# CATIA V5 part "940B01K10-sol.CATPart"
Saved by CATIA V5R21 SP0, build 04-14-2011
Part number: 940B01K10-sol
Bounding box of the stored display mesh (mm): x -77.949 to 0.051, y -15.698 to 19.302, z -6.85 to 7.15
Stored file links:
  C:\Users\ALI OZGUN\Desktop\alhan\940B01K10-sol.CATPart
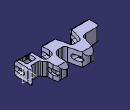
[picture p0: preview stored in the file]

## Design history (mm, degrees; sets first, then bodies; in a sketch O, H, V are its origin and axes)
Set1 "CURVE"
  DatumCurve1 to DatumCurve105
Set2 "SURFACE"
  Plane1: type 1Curve, Element1 DatumCurve19
  Sketch1 on Plane1, origin (0, 0, -3.1959), H (1, 0, 0), V (0, -1, 0)
    line L1 (49.4472, 15.9983) -> (32.7694, 15.9983)
    line L2 (48.5473, -19.0017) -> (65.7661, -19.0017)
    line L3 (-61.2339, -0.5841) -> (-61.2339, 15.0809)
    line L4 (65.7661, -19.0017) -> (65.7661, 3.0782)
    point P1 (65.7661, -19.0017)
    line L5 (49.4472, 15.9983) -> (49.0081, 3.1001)
    line L6 (49.0081, 3.1001) -> (53.2715, -2.5577)
    line L7 (53.2715, -2.5577) -> (61.843, -2.5577)
    point P2 (49.0081, 3.1001)
    point P3 (53.2715, -2.5577)
    point P4 (49.4472, 15.9983)
    line L8 (61.843, -2.5577) -> (65.7661, 3.0782)
    point P5 (61.843, -2.5577)
    point P6 (65.7661, 3.0782)
    reference intersected line E1 through (0, 0) direction (0, 1) from yz-plane
    reference intersected line E2 through (0, 0) direction (0, 1) from yz-plane
    construction line L9 (41.1083, 0) -> (41.1083, 12.9106)
    construction line L10 (41.1083, 12.9106) -> (46.3559, 12.9106)
    construction line L11 (46.3559, 12.9106) -> (46.3559, 3.0133)
    construction line L12 (46.3559, 3.0133) -> (41.1083, 3.0133)
    point P7 (46.3559, 12.9106)
    point P8 (46.3559, 3.0133)
    point P9 (41.1083, 12.9106)
    point P10 (41.1083, 3.0133)
    line L13 (41.1083, 0) -> (50.5276, 0)
    line L14 (48.5473, -19.0017) -> (50.5276, 0)
    point P11 (50.5276, 0)
    point P12 (41.1083, 0)
    point P13 (48.5473, -19.0017)
    point P14 (35.8607, 12.9106)
    point P15 (41.1083, 12.9106)
    construction line L15 (41.1083, 12.9106) -> (35.8607, 12.9106)
    point P16 (35.8607, 3.0133)
    construction line L16 (35.8607, 12.9106) -> (35.8607, 3.0133)
    point P17 (41.1083, 3.0133)
    construction line L17 (35.8607, 3.0133) -> (41.1083, 3.0133)
    point P18 (31.6891, 0)
    point P19 (41.1083, 0)
    line L18 (41.1083, 0) -> (31.6891, 0)
    point P20 (33.6694, -19.0017)
    line L19 (33.6694, -19.0017) -> (31.6891, 0)
    point P21 (16.4506, -19.0017)
    line L20 (33.6694, -19.0017) -> (16.4506, -19.0017)
    point P22 (16.4506, 3.0782)
    line L21 (16.4506, -19.0017) -> (16.4506, 0)
    point P23 (20.3736, -2.5577)
    line L22 (20.3736, -2.5577) -> (16.5464, 2.9405)
    point P24 (28.9451, -2.5577)
    line L23 (28.9451, -2.5577) -> (20.3736, -2.5577)
    point P25 (33.2086, 3.1001)
    line L24 (33.2086, 3.1001) -> (28.9451, -2.5577)
    point P26 (32.7694, 15.9983)
    line L25 (32.7694, 15.9983) -> (33.2086, 3.1001)
    axis line L26 (24.8802, -15.8106) -> (24.8802, 20.8842)
    line L27 (16.991, 15.9983) -> (16.5464, 2.9405)
    point P29 (13.8998, 3.0133)
    point P30 (13.8998, 12.9106)
    construction line L28 (13.8998, 12.9106) -> (13.8998, 3.0133)
    point P31 (8.6521, 0)
    line L29 (8.6521, 0) -> (16.4506, 0)
    point P32 (8.6521, 0)
    line L30 (8.6521, 0) -> (-0.2618, 0)
    point P33 (3.4045, 3.0133)
    point P34 (3.4045, 12.9106)
    construction line L31 (3.4045, 12.9106) -> (3.4045, 3.0133)
    point P35 (8.6521, 3.0133)
    construction line L32 (3.4045, 3.0133) -> (8.6521, 3.0133)
    point P36 (8.6521, 3.0133)
    construction line L33 (13.8998, 3.0133) -> (8.6521, 3.0133)
    point P37 (8.6521, 12.9106)
    construction line L34 (8.6521, 12.9106) -> (3.4045, 12.9106)
    point P38 (8.6521, 12.9106)
    construction line L35 (8.6521, 12.9106) -> (13.8998, 12.9106)
    point P39 (0.3133, 15.9983)
    line L36 (0.3133, 15.9983) -> (0.7524, 3.1001)
    line L37 (0.7524, 3.1001) -> (-3.8134, -2.9589)
    line L38 (16.991, 15.9983) -> (0.3133, 15.9983)
    line L39 (-0.2618, 0) -> (0.5916, -19.0017)
    line L40 (-12.1477, -5.1469) -> (-12.4932, -19.0017)
    line L41 (-3.8134, -2.9589) -> (-12.4906, -2.9589)
    line L42 (-12.4906, -2.9589) -> (-12.6654, 12.1222)
    line L43 (-29.6656, -3.0126) -> (-25.0164, 15.9983)
    line L44 (-39.0662, -3.1542) -> (-29.6656, -3.0126)
    line L45 (-44.327, 15.3928) -> (-39.0662, -3.1542)
    line L46 (-43.9186, 0.391) -> (-38.7475, -19.0017)
    line L47 (-43.9186, 0.391) -> (-61.2339, -0.5841)
    line L48 (-61.2339, 15.0809) -> (-44.327, 15.3928)
    line L49 (-16.4275, 15.9983) -> (-25.0164, 15.9983)
    line L50 (-16.4275, 15.9983) -> (-12.6654, 12.1222)
    line L51 (-24.9197, 0.2086) -> (-29.3974, -19.0017)
    line L52 (-24.9197, 0.2086) -> (-16.3942, 0.2086)
    line L53 (-16.3942, 0.2086) -> (-12.1477, -5.1469)
    line L54 (-29.3974, -19.0017) -> (-38.7475, -19.0017)
    line L55 (0.5916, -19.0017) -> (-12.4932, -19.0017)
    distance L2 L1 = 35
    distance L3 L4 = 127
    angle E1 L5 = 1.95
    angle E2 L6 = 37
    horizontal: L1 H, L2 H, L7 H, L10 H, L12 H, L13 H, L38 H, L41 H, L49 H, L52 H
    fix: L1, L9
    vertical: L3 V, L4 V, L9 V, L11 V, L26 V
    coincidence: P10 L9, L1 L38, P22 L22, P22 L21, L38 L49, L20 L54, L20 L55
    symmetry: P7 P14 L9, P9 P15 L9, L10 L15 L9, P8 P16 L9, L11 L16 L9, P10 P17 L9, L12 L17 L9, P11 P18 L9, P12 P19 L9, L13 L18 L9, P13 P20 L9, L14 L19 L9, P1 P21 L9, L2 L20 L9, P6 P22 L9, L4 L21 L9, P5 P23 L9, L8 L22 L9, P3 P24 L9, L7 L23 L9, P2 P25 L9, L6 L24 L9, P4 P26 L9, L5 L25 L9, L25 L27 L26, P16 P29 L26, P14 P30 L26, L16 L28 L26, P19 P31 L26, L18 L29 L26, P12 P32 L26, L13 L30 L26, P8 P33 L26, P7 P34 L26, L11 L31 L26, P10 P35 L26, L12 L32 L26, P17 P36 L26, L17 L33 L26, P9 P37 L26, L10 L34 L26, P15 P38 L26, L15 L35 L26, P4 P39 L26, L5 L36 L26, L6 L37 L26
  Sweep1: type Segment, GuideCrv Sketch1, Length1 4, Length2 5, Angle -1, DraftDirection (0, 0, 1)
  Sketch2 on yz-plane, origin (0, 0, 0), H (0, 1, 0), V (0, 0, 1)
    line L1 (-24.9191, -6.9968) -> (50.389, -6.9968)
    horizontal: L1 H
  Extrude1: Element1 Sketch2, Lim1 80, Lim2 80
  Trim1: Trimmed (Sweep1; Extrude1)
  Sketch3 on yz-plane, origin (0, 0, 0), H (0, 1, 0), V (0, 0, 1)
    line L1 (-48.3055, 0) -> (52.6647, 0)
    horizontal: L1 H
    coincidence: O L1
  Extrude2: Element1 Sketch3, Lim1 80, Lim2 80
  Trim2: Trimmed (Trim1; Extrude2)
  Extrude3: Element1 Sketch7, Lim1 10, Lim2 10
  Translate1: Direction (1, 0, 0), Length 32.6, ToTransfor Extrude3
  Extrude4: Element1 Sketch8, Lim1 10, Lim2 10
  Translate2: Direction (1, 0, 0), Length 32.8, ToTransfor Extrude4
  Sweep2: type Segment, GuideCrv Sketch11, Length1 10, Length2 5, Angle -1, DraftDirection (0, 0, 1)
  Translate3: Direction (1, 0, 0), Length -32.8, ToTransfor Sweep2
  Sketch4 on face of CloseSurface1, origin (0, 0, 0), H (1, 0, 0), V (0, 1, 0)
    line L1 (-3.8486, 19.8441) -> (1.0015, 13.5162)
  Sweep3: type Segment, GuideCrv Sketch4, Length1 10, Length2 5, Angle 1, DraftDirection (0, 0, 1)
  Plane2: type 1Curve, Element1 DatumCurve99
  Sketch5 on Plane2, origin (0, 0, -5.2979), H (1, 0, 0), V (0, -1, 0)
    line L1 (-37.6706, -7.3878) -> (-35.3775, -14.835)
    line L2 (-32.6098, -14.835) -> (-30.9175, -7.3878)
    offset line E2 (-36.4878, -14.835) -> (-31.7318, -14.835) from edge [face of Mirror1 | face of CloseSurface1]
    offset line E3 (-35.3775, -14.835) -> (-32.6098, -14.835) from edge [face of Mirror1 | face of CloseSurface1]
    line L3 (-37.6706, -7.3878) -> (-30.9175, -7.3878)
    point P5 (-36.4878, -7.3878)
    point P6 (-31.7318, -7.3878)
    construction line L4 (-36.4878, -14.835) -> (-36.4878, -7.3878)
    construction line L5 (-31.7318, -14.835) -> (-31.7318, -7.3878)
    distance E2 L3 = 7.4472
    perpendicularity: L4 E2, L4 L3, L5 E2, L5 L3
    coincidence: P5 L3, P6 L3
  Sweep4: type Segment, GuideCrv Sketch5, Length1 5, Length2 5, Angle -1, DraftDirection (0, 0, 1)
  Sketch6 on yz-plane, origin (0, 0, 0), H (0, 1, 0), V (0, 0, 1)
    line L1 (-47.946, -0.4507) -> (26.6531, -0.4507)
    horizontal: L1 H
  Extrude5: Element1 Sketch6, Lim1 100, Lim2 100
  Trim3: Trimmed (Sweep4; Extrude5)
  Sweep5: type Segment, GuideCrv Sketch12, Length1 5, Length2 5, Angle -1, DraftDirection (0, 0, 1)
  Trim4: Trimmed (Extrude5; Sweep5)
  MultiExtract1: ListOfMultiExtractConstraints (MultiExtractConstraint face of Split9; MultiExtractConstraint face of Fillet45; MultiExtractConstraint face of Split9; MultiExtractConstraint face of Fillet47; MultiExtractConstraint face of Split9; MultiExtractConstraint face of Split9; MultiExtractConstraint face of Fillet49; MultiExtractConstraint face of Fillet48; MultiExtractConstraint face of Fillet46; MultiExtractConstraint face of Split9)
  Extrapol1: ToExtrapol edge of MultiExtract1, Support MultiExtract1, Length 10
  Extrapol2: ToExtrapol edge [end face of Pocket4 | face of Pocket5 from Sketch15.E2], Support face of Pocket5 from Sketch15.E2, Length 10
  Trim5: Trimmed (Extrapol1; Extrapol2)
  Extrapol3: ToExtrapol edge of MultiExtract1, Support Trim5, Length 1
  Extrapol4: ToExtrapol edge [face of Pocket4 from Sketch14.L2 | face of CloseSurface1], Support face of Pocket4 from Sketch14.L2, Length 5
  Extrapol5: ToExtrapol edge [face of Pocket4 from Sketch14.L1 | face of Mirror1], Support face of Pocket4 from Sketch14.L1, Length 5
  Extrapol6: ToExtrapol edge [face of Mirror1 | face of Pocket4 from Sketch14.L4], Support face of Pocket4 from Sketch14.L4, Length 5
  Trim6: Trimmed (Extrapol6; Extrapol5; Extrapol4)
  Extrapol7: ToExtrapol edge [face of CloseSurface1 | face of Split10], Support face of Split10, Length 5
  Trim7: Trimmed (Extrapol7; Trim6)
  Extrapol8: ToExtrapol edge [face of CloseSurface1 | face of Pocket4 from Sketch14.L3], Support face of Pocket4 from Sketch14.L3, Length 5
  Trim8: Trimmed (Extrapol8; Trim7)
Set3
  CLDGeom1 "4_1.1"
  Plane3: type Offset, RefPlane yz-plane, Offset -63
  Plane4: type Offset, RefPlane face of Solid3, Offset 0.2, reversed
Body1 (main body)
  CloseSurface1: CloseElement Trim2
  Sketch7 on face of CloseSurface1, origin (0, 0, -6.9968), H (1, 0, 0), V (0, -1, 0)
    line L1 (3.5232, 12.867) -> (13.7904, 12.867)
    line L2 (13.7904, 12.867) -> (13.7904, 3.1238)
    line L3 (13.7904, 3.1238) -> (3.5232, 3.1238)
    line L4 (3.5232, 3.1238) -> (3.5232, 12.867)
    horizontal: L1 H, L3 H
    vertical: L2 V, L4 V
    fix: L4, L1
  Split1: SplitPlane Extrude3
  Split2: SplitPlane Translate1
  Sketch8 on face of CloseSurface1, origin (0, 0, -6.9968), H (1, 0, 0), V (0, -1, 0)
    line L1 (19.6709, -6.2611) -> (30.062, -6.2611)
    line L2 (30.062, -6.2611) -> (30.062, -15.6449)
    line L3 (30.062, -15.6449) -> (19.6709, -15.6449)
    line L4 (19.6709, -15.6449) -> (19.6709, -6.2611)
    horizontal: L1 H, L3 H
    vertical: L2 V, L4 V
    fix: L1, L4, L2
  Split3: SplitPlane Translate2
  Split4: SplitPlane Extrude4
  Sketch9 on face of CloseSurface1, origin (0, 0, -6.9968), H (1, 0, 0), V (0, -1, 0)
    line L1 (-8.0734, -6.1533) -> (-4.0044, -6.1533)
    line L2 (-4.0044, -6.1533) -> (-4.0044, -14.5157)
    line L3 (-4.0044, -14.5157) -> (-8.0734, -14.5157)
    line L4 (-8.0734, -14.5157) -> (-8.0734, -6.1533)
    horizontal: L1 H, L3 H
    vertical: L2 V, L4 V
  Pocket1: profile Sketch9, direction (0, 0, 1), length 20
  Sketch10 on face of CloseSurface1, origin (0, 0, -6.9968), H (1, 0, 0), V (0, -1, 0)
    line L1 (-16.7652, 4.7837) -> (-23.421, 4.7837)
    line L2 (-21.5701, 11.8402) -> (-16.7652, 11.8402)
    line L3 (-16.7652, 11.8402) -> (-16.7652, 4.7837)
    line L4 (-23.421, 4.7837) -> (-21.5701, 11.8402)
    horizontal: L1 H, L2 H
    vertical: L3 V
  Pocket2: profile Sketch10, direction (0, 0, 1), length 20
  Draft1: Angle 1, Neutral face of CloseSurface1, PullDir face of CloseSurface1, SupportToDraft (face of Split3; face of Split3; face of Split3; face of Split3; face of Split2; face of Split2; face of Split2; face of Split2; face of Split4; face of Split4; face of Split4; face of Split4; face of Split1; face of Split1; face of Split1; face of Split1; face of Pocket1 from Sketch9.L2; face of Pocket1 from Sketch9.L4; face of Pocket1 from Sketch9.L3; face of Pocket1 from Sketch9.L1; face of Pocket2 from Sketch10.L1; face of Pocket2 from Sketch10.L3; face of Pocket2 from Sketch10.L2; face of Pocket2 from Sketch10.L4)
  Chamfer1: length 2.85, angle 44, on edge [face of CloseSurface1 | face of CloseSurface1] (x8)
  Thickness1: Face (face of Chamfer1; face of Chamfer1; face of Chamfer1; face of Chamfer1), Thickness 0.15
  Thickness2: Face (face of Chamfer1; face of Chamfer1; face of Chamfer1; face of Chamfer1), Thickness 0.4
  Sketch11 on face of CloseSurface1, origin (0, 0, 0), H (1, 0, 0), V (0, 1, 0)
    line L1 (57.6565, 24.4948) -> (67.109, 12.822)
    line L2 (46.3763, 10.5649) -> (57.6565, 24.4948)
    angle V L2 = 39
    angle L1 V = 39
  Split5: SplitPlane Sweep2
  Split6: SplitPlane Translate3
  Split7: SplitPlane Sweep3
  Thickness3: Face face of Split7, Thickness -0.1
  Fillet1: radius 0.75, on edge [face of CloseSurface1 | face of CloseSurface1]
  Fillet2: radius 4, on edge [face of Split6 | face of CloseSurface1]; edge [face of Split5 | face of CloseSurface1]
  Fillet3: radius 4.5, on edge [face of Split6 | face of CloseSurface1]; edge [face of Split5 | face of CloseSurface1]
  Fillet4: radius 4.5, on edge [face of Split6 | face of CloseSurface1]; edge [face of Split5 | face of CloseSurface1]
  Fillet5: radius 4.5, on edge [face of CloseSurface1 | face of Split5]; edge [face of CloseSurface1 | face of Split6]
  Fillet6: radius 3.5, on edge [face of CloseSurface1 | face of CloseSurface1] (x4)
  Fillet7: radius 3, on edge [face of Split7 | face of CloseSurface1]
  Fillet8: radius 3, on edge [face of Split7 | face of CloseSurface1]
  Fillet9: radius 4, on edge [face of CloseSurface1 | face of CloseSurface1]
  Fillet10: radius 3, on edge [face of CloseSurface1 | face of CloseSurface1]
  Fillet11: radius 3, on edge [face of CloseSurface1 | face of CloseSurface1]
  Fillet12: radius 3, on edge [face of CloseSurface1 | face of CloseSurface1]
  Fillet13: radius 3, on edge [face of CloseSurface1 | face of CloseSurface1]
  Fillet14: radius 3, on edge [face of CloseSurface1 | face of CloseSurface1]
  Fillet15: radius 3, on edge [face of CloseSurface1 | face of CloseSurface1]
  Fillet16: radius 3, on edge [face of CloseSurface1 | face of CloseSurface1]
  Fillet17: radius 3, on edge [face of CloseSurface1 | face of CloseSurface1] (x2)
  Fillet18: radius 0.75, on edge [face of CloseSurface1 | face of CloseSurface1]
  Fillet19: radius 0.75, on edge [face of CloseSurface1 | face of CloseSurface1]
  Fillet20: radius 3, on edge [face of CloseSurface1 | face of CloseSurface1] (x4)
  Fillet21: radius 0.75, on edge [face of CloseSurface1 | face of CloseSurface1] (x2)
  Fillet22: radius 3, on edge [face of CloseSurface1 | face of CloseSurface1] (x2)
  Fillet23: radius 4, on edge [face of CloseSurface1 | face of CloseSurface1]
  Fillet24: radius 3, on edge [face of CloseSurface1 | face of CloseSurface1]
  Fillet25: radius 1.5, on edge [face of CloseSurface1 | face of CloseSurface1] (x2)
  Fillet26: radius 3, on edge [face of CloseSurface1 | face of CloseSurface1] (x2)
  Fillet27: radius 3, on edge [face of CloseSurface1 | face of CloseSurface1]
  Fillet28: radius 0.5, on edge [face of CloseSurface1 | face of CloseSurface1]
  Fillet29: radius 0.5, on edge [face of CloseSurface1 | face of CloseSurface1]
  Fillet30: radius 2.75, on edge [face of Split4 | face of Split4] (x2); edge [face of Split3 | face of Split3] (x2)
  Fillet31: radius 2, on edge [face of Split4 | face of Split4] (x2); edge [face of Split3 | face of Split3] (x2)
  Fillet32: radius 2.75, on edge [face of Split2 | face of Split2] (x2)
  Fillet33: radius 2, on edge [face of Split2 | face of Split2] (x2)
  Fillet34: radius 1.5, on edge [face of Split1 | face of Split1] (x2)
  Fillet35: radius 1.75, on edge [face of Split1 | face of Split1] (x2)
  TritangentFillet1: Face1 face of Pocket1 from Sketch9.L4, Face2 face of Pocket1 from Sketch9.L2, RemoveFace face of Pocket1 from Sketch9.L1
  TritangentFillet2: Face1 face of Pocket1 from Sketch9.L4, Face2 face of Pocket1 from Sketch9.L2, RemoveFace face of Pocket1 from Sketch9.L3
  Fillet36: radius 1.75, on edge [face of Pocket2 from Sketch10.L2 | face of Pocket2 from Sketch10.L3]
  Fillet37: radius 1, on edge [face of Pocket2 from Sketch10.L4 | face of Pocket2 from Sketch10.L2]
  Fillet38: radius 1.5, on edge [face of Pocket2 from Sketch10.L4 | face of Pocket2 from Sketch10.L1]
  Fillet39: radius 1.75, on edge [face of Pocket2 from Sketch10.L3 | face of Pocket2 from Sketch10.L1]
  Fillet40: radius 0.5, on edge [face of CloseSurface1 | face of CloseSurface1] (x8)
  Fillet41: radius 0.5, on edge [face of Chamfer1 | face of CloseSurface1]
  Fillet42: radius 0.5, on edge [face of Chamfer1 | face of CloseSurface1]
  Fillet43: radius 0.5, on edge [face of Chamfer1 | face of CloseSurface1] (x2)
  Fillet44: radius 0.5, on edge [face of Chamfer1 | face of CloseSurface1] (x4)
  Thickness4: Face face of CloseSurface1, Thickness 0.15
  Mirror1: of the body so far, about face of CloseSurface1
  Split8: SplitPlane Trim3
  Sketch12 on Plane2, origin (0, 0, -5.2979), H (1, 0, 0), V (0, -1, 0)
    line L1 (-57.1409, 11.1692) -> (-47.5031, 11.1692)
    line L2 (-46.3543, 7.2877) -> (-46.3543, 4.9902)
    line L3 (-46.3543, 4.9902) -> (-57.1409, 4.9902)
    line L4 (-57.1409, 4.9902) -> (-57.1409, 11.1692)
    line L5 (-47.5031, 11.1692) -> (-46.3543, 7.2877)
    horizontal: L1 H, L3 H
    vertical: L2 V, L4 V
  Split9: SplitPlane Trim4
  Fillet45: radius 2, on edge [face of Split9 | face of Split9]
  Fillet46: radius 2, on edge [face of Split9 | face of Split9]
  Fillet47: radius 1.9, on edge [face of Split9 | face of Split9]
  Fillet48: radius 2, on edge [face of Split9 | face of Split9]
  Fillet49: radius 2, on edge [face of Split9 | face of Split9]
  Fillet50: radius 2, on edge [face of Split8 | face of Split8]
  Fillet51: radius 2, on edge [face of Split8 | face of Split8]
  Fillet52: radius 1.5, on edge [face of Split8 | face of Split8] (x2)
  Sketch13 on yz-plane, origin (0, 0, 0), H (0, 1, 0), V (0, 0, 1)
    line L1 (4.7142, -2.0988) -> (16.0181, -2.0988)
    line L2 (16.0181, -2.0988) -> (16.0181, 2.7411)
    line L3 (16.0181, 2.7411) -> (4.7142, 2.7411)
    line L4 (4.7142, 2.7411) -> (4.7142, -2.0988)
    horizontal: L1 H, L3 H
    vertical: L2 V, L4 V
  Pocket3: profile Sketch13, direction (-1, 0, 0), length 111, opposite side length 100
  Sketch14 on yz-plane, origin (0, 0, 0), H (0, 1, 0), V (0, 0, 1)
    line L1 (-13.6557, 2.8812) -> (-2.4057, 2.8812)
    line L2 (-2.4057, 2.8812) -> (-2.4057, -2.1188)
    line L3 (-2.4057, -2.1188) -> (-13.6557, -2.1188)
    line L4 (-13.6557, -2.1188) -> (-13.6557, 2.8812)
    distance L1 L3 = 5
    distance L4 L2 = 11.25
    horizontal: L1 H, L3 H
    vertical: L2 V, L4 V
    fix: L1
  Pocket4: profile Sketch14, direction (-1, 0, 0), length 55, opposite side length 100
  Sketch15 on Plane3, origin (-63, 0, 0), H (0, 1, 0), V (0, 0, 1)
    projected line E1 (16.0181, 2.7411) -> (4.7142, 2.7411) from edge [face of Pocket3 from Sketch13.L3 | face of Mirror1]
    projected line E2 (2.9895, 2.7411) -> (-6.2509, 2.7411) from edge [face of Pocket3 from Sketch13.L3 | face of Mirror1]
    projected line E3 (16.0181, -2.0988) -> (4.7142, -2.0988) from edge [face of CloseSurface1 | face of Pocket3 from Sketch13.L1]
    projected line E4 (2.9895, -2.0988) -> (-6.2509, -2.0988) from edge [face of CloseSurface1 | face of Pocket3 from Sketch13.L1]
    line L1 (-6.2509, -2.0988) -> (-6.2509, 2.7411)
    line L2 (2.9895, 2.7411) -> (2.9895, -2.0988)
    vertical: L1 V, L2 V
  Pocket5: profile Sketch15, direction (1, 0, 0), length 11
  Split10: SplitPlane Extrapol3
  Split11: SplitPlane Trim8
  Align1: SewingRemoveFace face of Split11, SplitPlane face of Split10
  Thickness5: Face (face of Split11; face of Pocket5 from Sketch15.E4), Thickness 0.15
  Align2: SewingRemoveFace face of Pocket5 from Sketch15.E4, SplitPlane face of Split11
  RemoveFace1: RemoveFaces (face of Pocket4 from Sketch14.L3; face of Pocket4 from Sketch14.L1; face of Pocket4 from Sketch14.L4; face of Pocket4 from Sketch14.L2; face of Pocket4 from Sketch14.L2; face of Pocket4 from Sketch14.L1; face of Pocket4 from Sketch14.L3; face of Pocket4 from Sketch14.L4; face of Pocket4 from Sketch14.L4; face of Pocket4 from Sketch14.L1; face of Pocket4 from Sketch14.L2; face of Pocket4 from Sketch14.L3)
  RemoveFace2: RemoveFaces (face of Pocket3 from Sketch13.L3; face of Pocket3 from Sketch13.L4; face of Pocket3 from Sketch13.L1; face of Pocket3 from Sketch13.L2; face of Pocket3 from Sketch13.L4; face of Pocket3 from Sketch13.L3; face of Pocket3 from Sketch13.L1; face of Pocket3 from Sketch13.L2; face of Pocket3 from Sketch13.L3; face of Pocket3 from Sketch13.L4; face of Pocket3 from Sketch13.L2; face of Pocket3 from Sketch13.L1)
  Draft2: Angle 0, Neutral xy-plane, PullDir xy-plane, SupportToDraft (face of Mirror1; face of Split1; face of Mirror1; face of Split2; face of Mirror1; face of Fillet31; face of Mirror1; face of Fillet31; face of Mirror1; face of Fillet36)
  RemoveFace3: RemoveFaces (face of Split10; face of Split11; face of Split10; face of Split10; face of Split10; face of Split10; face of Split10; face of Split10; face of Split10; face of Split10; face of Split10; end face of Pocket5; face of Split11; face of Split11; face of Pocket5 from Sketch15.L1; face of Split11)
  Sketch16 on face of CloseSurface1, origin (0, 0, -6.9968), H (1, 0, 0), V (0, -1, 0)
    projected curve E1 from edge [face of Split11 | face of Split10]
    projected line E2 (-55.083, 5.0483) -> (-48.3121, 5.0483) from edge [face of Split10 | face of Split11]
    projected curve E3 from edge [face of Split11 | face of Split10]
    projected line E4 (-46.4946, 7.5571) -> (-47.1226, 9.6789) from edge [face of Split10 | face of Split11]
    projected arc E5 centre (-48.414, 6.9893) radius 2.0016 from (-46.4124, 6.9896) to (-46.4946, 7.5571) ccw from edge [face of Split11 | face of Split10]
    projected curve E6 from edge [face of Split11 | face of Split10]
    projected line E7 (-49.0401, 11.1111) -> (-55.083, 11.1111) from edge [face of Split10 | face of Split11]
    projected curve E8 from edge [face of Split11 | face of Split10]
    line L1 (-57.0827, 9.1114) -> (-57.0827, 7.048)
    projected line E9 (-46.4124, 6.948) -> (-46.4124, 6.9896) from edge [face of Split10 | face of Split11]
    projected line E10 (-33.4926, -7.4437) -> (-34.8869, -7.4437) from edge [face of Split8 | face of Pocket3 from Sketch13.L1]
    projected curve E11 from edge [face of Pocket3 from Sketch13.L1 | face of Fillet51]
    projected line E12 (-32.3891, -13.6117) -> (-31.5426, -9.8864) from edge [face of Split8 | face of Pocket3 from Sketch13.L1]
    projected curve E13 from edge [face of Pocket3 from Sketch13.L1 | face of Fillet52]
    projected curve E14 from edge [face of Fillet52 | face of Pocket3 from Sketch13.L1]
    projected line E15 (-34.2288, -14.7792) -> (-33.8515, -14.7792) from edge [face of Split8 | face of Pocket3 from Sketch13.L1]
    projected line E16 (-36.798, -10.0318) -> (-35.6622, -13.7207) from edge [face of Split8 | face of Pocket3 from Sketch13.L1]
    projected curve E17 from edge [face of Fillet50 | face of Pocket3 from Sketch13.L1]
    vertical: L1 V
  Draft3: Angle 0, Neutral face of Pocket3 from Sketch13.L1, PullDir face of Pocket3 from Sketch13.L1, SupportToDraft face of Fillet52
  RemoveFace4: RemoveFaces (face of Pocket3 from Sketch13.L1; face of Pocket3 from Sketch13.L4; face of Pocket3 from Sketch13.L3; face of Pocket3 from Sketch13.L2; face of Split8; face of Fillet52; face of Split8; face of Fillet52; face of Split8; face of Fillet50; face of Split8; face of Fillet51)
  Pocket6: profile Sketch16, direction (0, 0, 1), up to xy-plane
  Sketch17 on yz-plane, origin (0, 0, 0), H (0, 1, 0), V (0, 0, 1)
    construction line L1 (-11.1983, 0.15) -> (-5.1983, 0.15)
    point P1 (-11.1983, 0.15)
    line L2 (-11.1983, 2.65) -> (-5.1983, 2.65)
    line L3 (-5.1983, -2.35) -> (-11.1983, -2.35)
    arc A1 centre (-5.1983, 0.15) radius 2.5 from (-5.1983, 2.65) to (-5.1983, -2.35) cw
    arc A2 centre (-11.1983, 0.15) radius 2.5 from (-11.1983, -2.35) to (-11.1983, 2.65) cw
    point P3 (-11.1983, 2.65)
    point P4 (-5.1983, 2.65)
    point P5 (-5.1983, -2.35)
    point P6 (-11.1983, -2.35)
    reference projected line E1 (12.9961, 0.15) -> (-0.8745, 0.15) from edge [face of Mirror1 | face of CloseSurface1]
    construction line L4 (19.0601, 0.15) -> (-16.0567, 0.15)
    axis line L5 (1.5017, 0.15) -> (1.5017, 16.5006)
    point P7 (1.5017, 0.15)
    construction line L6 (14.2017, 0.15) -> (8.2017, 0.15)
    point P11 (14.2017, 2.65)
    point P12 (8.2017, 2.65)
    point P13 (8.2017, -2.35)
    point P14 (14.2017, -2.35)
    line L7 (14.2017, 2.65) -> (8.2017, 2.65)
    line L8 (8.2017, -2.35) -> (14.2017, -2.35)
    arc A3 centre (8.2017, 0.15) radius 2.5 from (8.2017, 2.65) to (8.2017, -2.35) ccw
    arc A4 centre (14.2017, 0.15) radius 2.5 from (14.2017, -2.35) to (14.2017, 2.65) ccw
    distance L1 L2 = 2.5
    distance P1 L5 = 12.7
    length L1 = 6
    horizontal: L1 H, L4 H
    tangency: A1 L2, A2 L2, A1 L3, A2 L3
    coincidence: L1 E1
    midpoint: P7 L4
    vertical: L5 V
    symmetry: L1 L6 L5, P3 P11 L5, P4 P12 L5, P5 P13 L5, P6 P14 L5, L2 L7 L5, L3 L8 L5, A1 A3 L5, A2 A4 L5
  Sketch18 on xy-plane, origin (0, 0, 0), H (1, 0, 0), V (0, 1, 0)
    line L1 (-59.6762, 27.1723) -> (64.7084, 27.1723)
    line L2 (64.7084, 27.1723) -> (64.7084, -29.9789)
    line L3 (64.7084, -29.9789) -> (-59.6762, -29.9789)
    line L4 (-59.6762, -29.9789) -> (-59.6762, 27.1723)
    reference projected line E1 through (65.2084, 0) direction (0, -1) from axis of face of Mirror1
    reference projected line E2 (-60.6762, -12.5832) -> (-60.6762, -0.0059) from edge [face of Mirror1 | face of Mirror1]
    distance L2 E1 = 0.5
    distance L4 E2 = 1
    horizontal: L1 H, L3 H
    vertical: L2 V, L4 V
  Pocket7: profile Sketch18, direction (0, 0, -1), length 94, mirrored extent, outer side
  Thickness6: Face face of Pocket7 from Sketch18.L4, Thickness 2
  Thickness7: Face face of Pocket7 from Sketch18.L4, Thickness 1.115
  Pocket8: profile Sketch17, direction (-1, 0, 0), length 94, mirrored extent
  Sketch19 on yz-plane, origin (0, 0, 0), H (0, 1, 0), V (0, 0, 1)
    arc A1 centre (-5.1983, 0.15) radius 2.5 from (-5.1983, 2.65) to (-5.1983, -2.35) ccw
    point P10 (-5.1983, -2.35)
    line L1 (-11.1983, 2.65) -> (-5.1983, 2.65)
    arc A2 centre (-11.1982, 0.15) radius 2.5 from (-11.1983, 2.65) to (-13.6983, 0.15) ccw
    arc A3 centre (-11.1982, 0.15) radius 2.5 from (-13.6983, 0.15) to (-11.1983, -2.35) ccw
    line L2 (-5.1983, -2.35) -> (-11.1983, -2.35)
    construction arc A4 centre (-5.1983, 0.15) radius 2.5 from (-2.6983, 0.15) to (-5.1983, 2.65) ccw
    coincidence: A1 A4, L2 P10
  Pad1: profile Sketch19, direction (-1, 0, 0), length 94, opposite side up to face of Pocket6 from Sketch16.L1
  Split12: SplitPlane face of Pocket7 from Sketch18.L4
Body2
  Solid1: linked copy from another document
  Translate4: Direction zx-plane, Length -19, ToTransfor Solid1
Body3
  Solid2: solid without history
  Translate5: Direction edge [face of Solid3 | face of Solid3], Length 15, ToTransfor Solid2
Body4
  Solid3: solid without history
  Split13: SplitPlane face of Solid3
  Body5
    Sketch20 on face of Solid3, origin (0, 0, -6.85), H (1, 0, 0), V (0, -1, 0)
      line L1 (-77.9488, 12.497) -> (-77.9488, 2.8937)
      line L2 (-75.055, 0) -> (-62.8479, 0)
      line L3 (-58.0492, -3.5955) -> (-54.3874, -16.1072)
      line L4 (-50.1239, -19.3017) -> (-48.9356, -19.3017)
      line L5 (-43.8676, -15.3198) -> (-40.7729, -2.6121)
      point P1 (-40.1368, 0)
      line L6 (-37.4484, 0) -> (-33.9228, 0)
      line L7 (-28.7341, -2.6853) -> (-28.7254, -2.6976)
      line L8 (-26.6939, -9.0873) -> (-26.6939, -16.7891)
      point P2 (-26.6939, -19.3017)
      line L9 (-24.1812, -19.3017) -> (-23.1488, -19.3017)
      line L10 (-19.4647, -17.5249) -> (-18.7392, -16.613)
      line L11 (-16.7488, -10.9137) -> (-16.7488, -5.4517)
      line L12 (-18.0368, -2.7398) -> (-21.509, -2.7398)
      line L13 (-27.885, 3.6363) -> (-27.885, 12.2509)
      line L14 (-27.885, 12.2509) -> (-31.292, 15.6983)
      line L15 (-31.292, 15.6983) -> (-40.4229, 15.6983)
      line L16 (-40.4229, 15.6983) -> (-44.4156, -0.6971)
      line L17 (-47.975, -3.4937) -> (-52.1939, -3.4937)
      line L18 (-55.7282, -0.8455) -> (-59.3074, 11.3836)
      line L19 (-65.0658, 15.6983) -> (-74.7475, 15.6983)
      projected line E1 (-16.6488, -5.3517) -> (-13.9346, -2.6375) from edge [face of Solid3 | face of Solid3]
      projected line E2 (-16.7488, -5.4517) -> (-13.9346, -2.6375) from edge [face of Solid3 | face of Solid3]
      projected line E3 (-18.1594, -2.8624) -> (-16.5488, -1.2517) from edge [face of Solid3 | face of Solid3]
      projected line E4 (-18.0368, -2.7398) -> (-16.5488, -1.2517) from edge [face of Solid3 | face of Solid3]
      line L20 (-13.9346, -2.6375) -> (-16.5488, -1.2517)
      arc A1 centre (-21.509, 3.6363) radius 6.376 from (-21.509, -2.7398) to (-27.885, 3.6363) cw
      arc A2 centre (-37.7581, -9.0873) radius 11.0643 from (-28.7254, -2.6976) to (-26.6939, -9.0873) cw
      arc A3 centre (-33.9228, -6.3557) radius 6.3557 from (-33.9228, 0) to (-28.7341, -2.6853) cw
      arc A4 centre (-37.4484, -3.4217) radius 3.4217 from (-37.4484, 0) to (-40.7729, -2.6121) ccw
      arc A5 centre (-25.9033, -10.9137) radius 9.1545 from (-16.7488, -10.9137) to (-18.7392, -16.613) cw
      arc A6 centre (-23.1488, -14.5941) radius 4.7077 from (-23.1488, -19.3017) to (-19.4647, -17.5249) ccw
      arc A7 centre (-24.1812, -16.7891) radius 2.5127 from (-26.6939, -16.7891) to (-24.1812, -19.3017) ccw
      arc A8 centre (-48.9356, -14.0856) radius 5.2161 from (-48.9356, -19.3017) to (-43.8676, -15.3198) ccw
      arc A9 centre (-50.1239, -14.8594) radius 4.4424 from (-54.3874, -16.1072) to (-50.1239, -19.3017) ccw
      arc A10 centre (-62.8479, -5) radius 5 from (-62.8479, 0) to (-58.0492, -3.5955) cw
      arc A11 centre (-52.1939, 0.1889) radius 3.6826 from (-55.7282, -0.8455) to (-52.1939, -3.4937) ccw
      arc A12 centre (-47.975, 0.1697) radius 3.6634 from (-47.975, -3.4937) to (-44.4156, -0.6971) ccw
      arc A13 centre (-75.055, 2.8937) radius 2.8937 from (-77.9488, 2.8937) to (-75.055, 0) ccw
      arc A14 centre (-74.7475, 12.497) radius 3.2013 from (-77.9488, 12.497) to (-74.7475, 15.6983) cw
      arc A15 centre (-65.0658, 9.6983) radius 6 from (-65.0658, 15.6983) to (-59.3074, 11.3836) cw
      reference intersected line E5 (49.3512, -5.3517) -> (49.3512, -15.4984) from face of Solid3
      reference projected line E6 (-8.3488, 15.6983) -> (-12.6313, 15.6983) from edge [face of Solid3 | face of Solid3]
      reference projected line E7 (-0.0488, -5.3517) -> (-0.0488, -15.4984) from edge [face of Solid3 | face of Solid3]
      radius A1 = 6.376
      radius A2 = 11.0643
      radius A3 = 6.3557
      radius A4 = 3.4217
      radius A5 = 9.1545
      radius A6 = 4.7077
      radius A7 = 2.5127
      radius A8 = 5.2161
      radius A9 = 4.4424
      radius A10 = 5
      radius A11 = 3.6826
      radius A12 = 3.6634
      radius A13 = 2.8937
      radius A14 = 3.2013
      radius A15 = 6
      distance E5 L1 = 127.3
      angle L3 L5 = 30
      distance L4 L15 = 35
      distance L2 H = 0
      angle L16 L13 = 13.6866
      distance L11 E7 = 16.7
      distance L18 L3 = 3
      distance L16 L5 = 3.9924
      vertical: L1 V, L11 V, L13 V
      horizontal: L2 H, L4 H, L6 H, L9 H, L12 H, L15 H, L17 H, L19 H
      coincidence: P1 H, P2 L4, L6 P1, L5 P1, L8 P2, L9 P2, E6 L15, L19 L15
      tangency: A1 L12, A1 L13, A2 L7, A2 L8, A3 L6, A3 L7, A4 L6, A4 L5, A5 L11, A5 L10, A6 L9, A6 L10, A7 L8, A7 L9, A8 L4, A8 L5, A9 L3, A9 L4, A10 L2, A10 L3, A11 L18, A11 L17, A12 L17, A12 L16, A13 L1, A13 L2, A14 L1, A14 L19, A15 L19, A15 L18
      parallelism: L11 L8
    Pad2: profile Sketch20, direction (0, 0, 1), length 14
    Sketch21 on yz-plane, origin (0, 0, 0), H (0, 1, 0), V (0, 0, 1)
      projected line E1 (-5.1983, 2.65) -> (-11.1983, 2.65) from edge [face of Solid2 | face of Solid2]
      projected arc E2 centre (-11.1982, 0.15) radius 2.5 from (-11.1983, 2.65) to (-13.6983, 0.15) ccw from edge [face of Solid2 | face of Solid2]
      projected arc E3 centre (-11.1982, 0.15) radius 2.5 from (-13.6983, 0.15) to (-11.1983, -2.35) ccw from edge [face of Solid2 | face of Solid2]
      projected line E4 (-5.1983, -2.35) -> (-11.1983, -2.35) from edge [face of Solid2 | face of Solid2]
      projected arc E5 centre (-5.1982, 0.15) radius 2.5 from (-4.1662, -2.127) to (-2.6983, 0.15) ccw from edge [face of Solid2 | face of Solid2]
      projected arc E6 centre (-5.1983, 0.15) radius 2.5 from (-5.1983, -2.35) to (-4.1662, -2.127) ccw from edge [face of Solid2 | face of Solid2]
      projected arc E7 centre (-5.1982, 0.15) radius 2.5 from (-2.6983, 0.15) to (-4.1662, 2.427) ccw from edge [face of Solid2 | face of Solid2]
      projected arc E8 centre (-5.1983, 0.15) radius 2.5 from (-4.1662, 2.427) to (-5.1983, 2.65) ccw from edge [face of Solid2 | face of Solid2]
      projected arc E9 centre (8.2017, 0.15) radius 2.5 from (8.2017, 2.65) to (8.2017, -2.35) ccw from edge [face of Solid2 | face of Solid2]
      projected line E10 (8.2017, 2.65) -> (14.2017, 2.65) from edge [face of Solid2 | face of Solid2]
      projected arc E11 centre (14.2017, 0.15) radius 2.5 from (15.7359, 2.1239) to (14.2017, 2.65) ccw from edge [face of Solid2 | face of Solid2]
      projected arc E12 centre (14.2018, 0.15) radius 2.5 from (16.7017, 0.15) to (15.7359, 2.1239) ccw from edge [face of Solid2 | face of Solid2]
      projected arc E13 centre (14.2018, 0.15) radius 2.5 from (15.7359, -1.8239) to (16.7017, 0.15) ccw from edge [face of Solid2 | face of Solid2]
      projected arc E14 centre (14.2017, 0.15) radius 2.5 from (14.2017, -2.35) to (15.7359, -1.8239) ccw from edge [face of Solid2 | face of Solid2]
      projected line E15 (14.2017, -2.35) -> (8.2017, -2.35) from edge [face of Solid2 | face of Solid2]
    Pocket9: profile Sketch21, direction (-1, 0, 0), length 129
    Sketch22 on start face of Pad2, origin (0, 0, -6.85), H (1, 0, 0), V (0, -1, 0)
      projected line E1 (-23.0734, -12.4815) -> (-23.0734, -8.1875) from edge [face of Solid2 | face of Solid2]
      projected arc E2 centre (-21.0389, -8.1878) radius 2.0345 from (-19.0043, -8.1875) to (-23.0734, -8.1875) ccw from edge [face of Solid2 | face of Solid2]
      projected line E3 (-19.0044, -8.1875) -> (-19.0044, -12.4815) from edge [face of Solid2 | face of Solid2]
      projected arc E4 centre (-21.0389, -12.4811) radius 2.0345 from (-23.0734, -12.4815) to (-19.0044, -12.4815) ccw from edge [face of Solid2 | face of Solid2]
      projected line E5 (-31.8873, 9.9683) -> (-31.8873, 6.6556) from edge [face of Solid2 | face of Solid2]
      projected arc E6 centre (-33.637, 9.9684) radius 1.7496 from (-31.8873, 9.9683) to (-33.6371, 11.718) ccw from edge [face of Solid2 | face of Solid2]
      projected line E7 (-35.7044, 11.718) -> (-33.6371, 11.718) from edge [face of Solid2 | face of Solid2]
      projected arc E8 centre (-35.7045, 10.7182) radius 0.9998 from (-35.7044, 11.718) to (-36.6716, 10.9719) ccw from edge [face of Solid2 | face of Solid2]
      projected line E9 (-37.7695, 6.7862) -> (-36.6716, 10.9719) from edge [face of Solid2 | face of Solid2]
      projected arc E10 centre (-36.319, 6.4055) radius 1.4997 from (-37.7695, 6.7862) to (-36.3188, 4.9059) ccw from edge [face of Solid2 | face of Solid2]
      projected line E11 (-33.6371, 4.9059) -> (-36.3188, 4.9059) from edge [face of Solid2 | face of Solid2]
      projected arc E12 centre (-33.637, 6.6555) radius 1.7496 from (-33.6371, 4.9059) to (-31.8873, 6.6556) ccw from edge [face of Solid2 | face of Solid2]
      projected line E13 (-48.4926, -7.4437) -> (-49.8869, -7.4437) from edge [face of Solid2 | face of Solid2]
      projected curve E14 from edge [face of Solid2 | face of Solid2]
      projected line E15 (-51.798, -10.0318) -> (-50.6622, -13.7207) from edge [face of Solid2 | face of Solid2]
      projected curve E16 from edge [face of Solid2 | face of Solid2]
      projected curve E17 from edge [face of Solid2 | face of Solid2]
      projected line E18 (-49.2288, -14.7792) -> (-48.8515, -14.7792) from edge [face of Solid2 | face of Solid2]
      projected line E19 (-47.3891, -13.6117) -> (-46.5426, -9.8864) from edge [face of Solid2 | face of Solid2]
      projected curve E20 from edge [face of Solid2 | face of Solid2]
      projected line E21 (-64.0401, 11.1111) -> (-70.083, 11.1111) from edge [face of Solid2 | face of Solid2]
      projected curve E22 from edge [face of Solid2 | face of Solid2]
      projected line E23 (-61.4946, 7.5571) -> (-62.1226, 9.6789) from edge [face of Solid2 | face of Solid2]
      projected curve E24 from edge [face of Solid2 | face of Solid2]
      projected line E25 (-70.083, 5.0483) -> (-63.3121, 5.0483) from edge [face of Solid2 | face of Solid2]
      projected curve E26 from edge [face of Solid2 | face of Solid2]
      projected line E27 (-72.0827, 9.1114) -> (-72.0827, 7.048) from edge [face of Solid2 | face of Solid2]
      projected curve E28 from edge [face of Solid2 | face of Solid2]
      projected arc E29 centre (-63.414, 6.9893) radius 2.0016 from (-61.4124, 6.9896) to (-61.4946, 7.5571) ccw from edge [face of Solid2 | face of Solid2]
      projected line E30 (-61.4124, 6.948) -> (-61.4124, 6.9896) from edge [face of Solid2 | face of Solid2]
    Pocket10: profile Sketch22, direction (0, 0, 1), length 6
    Sketch23 on face of Pad2 from Sketch20.L1, origin (-77.9488, 0, 0), H (0, -1, 0), V (0, 0, 1)
      projected line E1 (5.1983, 2.65) -> (11.1983, 2.65) from edge [face of Pocket9 from Sketch21.E1 | face of Pad2 from Sketch20.L1]
      projected line E2 (5.1982, 2.65) -> (11.1983, 2.65) from edge [face of Pocket9 from Sketch21.E1 | face of Pad2 from Sketch20.L1]
      point P2 (11.1983, 2.65)
      projected arc E3 centre (11.1982, 0.15) radius 2.5 from (12.497, 2.2862) to (11.1983, 2.65) ccw from edge [face of Pocket9 from Sketch21.E2 | face of Pad2 from Sketch20.L1]
      point P4 (11.1983, 2.65)
      projected arc E4 centre (11.1982, 0.15) radius 2.5 from (13.6983, 0.15) to (12.497, 2.2862) ccw from edge [face of Pad2 from Sketch20.A14 | face of Pocket9 from Sketch21.E2]
      projected arc E5 centre (11.1982, 0.15) radius 2.5 from (12.497, -1.9862) to (13.6983, 0.15) ccw from edge [face of Pocket9 from Sketch21.E3 | face of Pad2 from Sketch20.A14]
      projected arc E6 centre (11.1982, 0.15) radius 2.5 from (11.1983, -2.35) to (12.497, -1.9862) ccw from edge [face of Pocket9 from Sketch21.E3 | face of Pad2 from Sketch20.L1]
      point P9 (11.1983, -2.35)
      projected line E7 (5.1983, -2.35) -> (11.1983, -2.35) from edge [face of Pad2 from Sketch20.L1 | face of Pocket9 from Sketch21.E4]
      projected line E8 (5.1982, -2.35) -> (11.1983, -2.35) from edge [face of Pad2 from Sketch20.L1 | face of Pocket9 from Sketch21.E4]
      point P12 (11.1983, -2.35)
      arc A1 centre (5.1982, 0.15) radius 2.5 from (5.1982, -2.35) to (5.1982, 2.65) ccw
      reference projected arc E9 centre (5.1982, 0.15) radius 2.5 from (4.1662, 2.427) to (2.8937, 1.1191) ccw from edge [face of Pocket9 from Sketch21.E7 | face of Pad2 from Sketch20.L1]
      reference projected arc E10 centre (5.1982, 0.15) radius 2.5 from (4.1662, 2.427) to (2.8937, 1.1191) ccw from edge [face of Pocket9 from Sketch21.E7 | face of Pad2 from Sketch20.L1]
      concentricity: A1 E9
      coincidence: A1 E10, P2 P4, P9 P12
    Pad3: profile Sketch23, direction (1, 0, 0), up to face of Pocket10 from Sketch22.E27
    Sketch24 on start face of Pad2, origin (0, 0, -6.85), H (1, 0, 0), V (0, -1, 0)
      projected arc E1 centre (-74.7475, 12.497) radius 3.2013 from (-74.7475, 15.6983) to (-77.9488, 12.497) ccw from edge [face of Pad2 from Sketch20.A14 | start face of Pad2]
    Pocket11: profile Sketch24, direction (0, 0, 1), length 43
  Add1: tool Body5
  Split14: SplitPlane face of Solid3
  Split15: SplitPlane face of Solid3
  Split16: SplitPlane face of Solid3
  Split17: SplitPlane face of Solid3
  Split18: SplitPlane face of Solid3
  Fillet53: radius 1.5, on edge [face of Pad2 | face of Pad2 from Sketch20.L12]; edge [face of Pad2 from Sketch20.L11 | face of Pad2]; edge [face of Solid3 | face of Pad2]; edge [face of Solid3 | face of Solid3] (x10)
  Split19: SplitPlane Plane4
  RemoveFace5: RemoveFaces (face of Solid3; face of Solid3; face of Solid3; face of Solid3)
  Sketch25 on face of Solid3, origin (-0.0488, 0, 0), H (0, -1, 0), V (0, 0, 1)
    projected line E1 (-4.9124, -6.85) -> (-4.9124, 7.15) from edge [face of Solid3 | face of Fillet53]
  Pocket12: profile Sketch25, direction (1, 0, 0), length 43, opposite side length 1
